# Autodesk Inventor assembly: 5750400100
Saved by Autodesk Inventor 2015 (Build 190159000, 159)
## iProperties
Created: 2020-07
Part Number: 5750400100
Checked By: TraceParts S.A.
Catalog Web Link: www.traceparts.com
Document SubType Name: Assembly
Designer: TraceParts
Company: TraceParts S.A.
Author: TraceParts
REFERENCE: 5750400100
DESIGN: HXBR-315 ECOWATT (230V50/60HZ) V5 - 5750400100
SUPPLIER: Soler & Palau
TraceParts.PartNumber: 10-20122018-119605
TraceParts.PartTitle: HXBR-ECOWATT
TraceParts.InstanceId: 10-20122018-1196058MFGNQRCDE99P5KFAQ7AH8UQ8
TraceParts.PartStatus: Published
TraceParts.PartVersion: 1.0.2
TRACEPARTS: TRACEPARTS
TraceParts.PartLanguage: en
TraceParts.ClassPath: SOLER_PALAU:10-20122018-119605
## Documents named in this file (3)
- C:\TPO v2\SharedFS\Outgoing\5750400100.iam
- C:\TPO v2\SharedFS\Outgoing\5750400100_01.ipt
- C:\TPO v2\SharedFS\Outgoing\5750400100_02.ipt
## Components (2 placed, 2 different names)
1. 5750400100_01:1
2. 5750400100_02:1
